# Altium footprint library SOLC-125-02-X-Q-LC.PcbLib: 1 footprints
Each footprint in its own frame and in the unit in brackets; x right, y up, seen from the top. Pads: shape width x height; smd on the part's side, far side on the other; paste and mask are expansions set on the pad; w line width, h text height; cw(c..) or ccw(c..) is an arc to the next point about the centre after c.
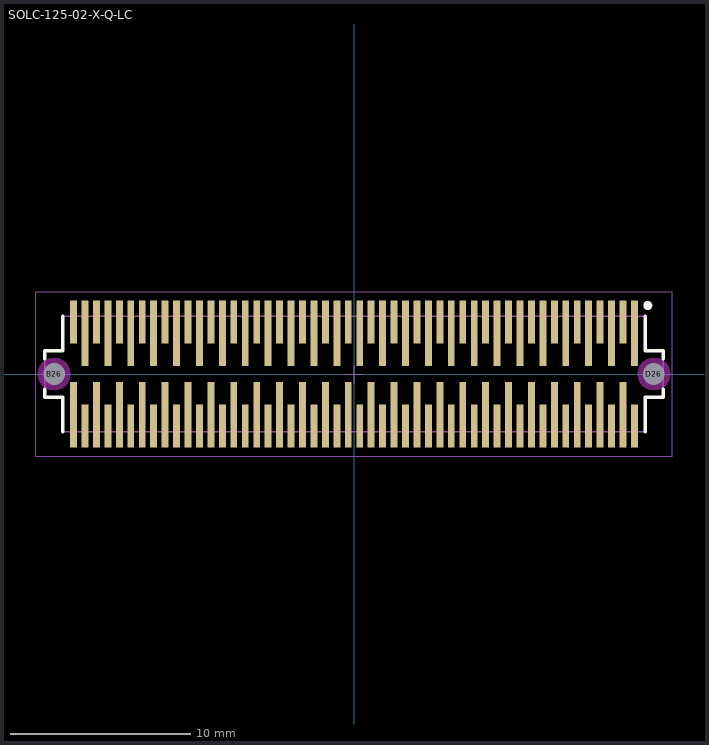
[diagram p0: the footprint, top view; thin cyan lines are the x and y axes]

## SOLC-125-02-X-Q-LC [mm] "1.27mm pitch, 100 pin, socket strip; 4 rows, w/locking clips, SMT"
height 4.62
pads (102):
  rect 0.38x2.36 smd mask+0: A1(14.922,2.885) A2(13.652,2.885) A3(12.383,2.885) A4(11.112,2.885) A5(9.842,2.885) A6(8.572,2.885) A7(7.302,2.885) A8(6.032,2.885) A9(4.763,2.885) A10(3.492,2.885) A11(2.222,2.885) A12(0.953,2.885) A13(-0.318,2.885) A14(-1.587,2.885) A15(-2.857,2.885) A16(-4.127,2.885) A17(-5.397,2.885) A18(-6.667,2.885) A19(-7.938,2.885) A20(-9.207,2.885) A21(-10.477,2.885) A22(-11.747,2.885) A23(-13.018,2.885) A24(-14.287,2.885) A25(-15.557,2.885) D1(15.557,-2.885) D2(14.287,-2.885) D3(13.018,-2.885) D4(11.747,-2.885) D5(10.477,-2.885) D6(9.207,-2.885) D7(7.938,-2.885) D8(6.667,-2.885) D9(5.397,-2.885) D10(4.127,-2.885) D11(2.857,-2.885) D12(1.587,-2.885) D13(0.318,-2.885) D14(-0.953,-2.885) D15(-2.222,-2.885) D16(-3.492,-2.885) D17(-4.763,-2.885) D18(-6.032,-2.885) D19(-7.302,-2.885) D20(-8.572,-2.885) D21(-9.842,-2.885) D22(-11.112,-2.885) D23(-12.383,-2.885) D24(-13.652,-2.885) D25(-14.922,-2.885)
  rect 0.38x3.63 smd mask+0: B1(15.557,2.25) B2(14.287,2.25) B3(13.018,2.25) B4(11.747,2.25) B5(10.477,2.25) B6(9.207,2.25) B7(7.938,2.25) B8(6.667,2.25) B9(5.397,2.25) B10(4.127,2.25) B11(2.857,2.25) B12(1.587,2.25) B13(0.318,2.25) B14(-0.953,2.25) B15(-2.222,2.25) B16(-3.492,2.25) B17(-4.763,2.25) B18(-6.032,2.25) B19(-7.302,2.25) B20(-8.572,2.25) B21(-9.842,2.25) B22(-11.112,2.25) B23(-12.383,2.25) B24(-13.652,2.25) B25(-14.922,2.25) C1(14.922,-2.25) C2(13.652,-2.25) C3(12.383,-2.25) C4(11.112,-2.25) C5(9.842,-2.25) C6(8.572,-2.25) C7(7.302,-2.25) C8(6.032,-2.25) C9(4.763,-2.25) C10(3.492,-2.25) C11(2.222,-2.25) C12(0.953,-2.25) C13(-0.318,-2.25) C14(-1.587,-2.25) C15(-2.857,-2.25) C16(-4.127,-2.25) C17(-5.397,-2.25) C18(-6.667,-2.25) C19(-7.938,-2.25) C20(-9.207,-2.25) C21(-10.477,-2.25) C22(-11.747,-2.25) C23(-13.018,-2.25) C24(-14.287,-2.25) C25(-15.557,-2.25)
  round 1 hole 1.2 unplated mask+0: B26(-16.637,0) D26(16.637,0)
Top Overlay:
  circle w0.25: c16.3,3.8 r0.125
  lines w0.2: -17.15,-0.85 -17.15,-1.3 -16.15,-1.3 -16.15,-3.2 ; -17.15,0.85 -17.15,1.3 -16.15,1.3 -16.15,3.2 ; 16.15,-3.2 16.15,-1.3 17.15,-1.3 17.15,-0.85 ; 16.15,3.2 16.15,1.3 17.15,1.3 17.15,0.85
Keep-Out Layer:
  pour cut-out: -15.729,0 -15.76,0.235 -15.851,0.454 -15.995,0.642 -16.183,0.786 -16.402,0.877 -16.637,0.908 -16.872,0.877 -17.091,0.786 -17.279,0.642 -17.423,0.454 -17.514,0.235 -17.545,0 -17.514,-0.235 -17.423,-0.454 -17.279,-0.642 -17.091,-0.786 -16.872,-0.877 -16.637,-0.908 -16.402,-0.877 -16.183,-0.786 -15.995,-0.642 -15.851,-0.454 -15.76,-0.235
  pour cut-out: 17.545,0 17.514,0.235 17.423,0.454 17.279,0.642 17.091,0.786 16.872,0.877 16.637,0.908 16.402,0.877 16.183,0.786 15.995,0.642 15.851,0.454 15.76,0.235 15.729,0 15.76,-0.235 15.851,-0.454 15.995,-0.642 16.183,-0.786 16.402,-0.877 16.637,-0.908 16.872,-0.877 17.091,-0.786 17.279,-0.642 17.423,-0.454 17.514,-0.235
Mechanical 12:
  lines w0.001: -17.15,-1.3 -16.15,-1.3 -16.15,-3.2 16.15,-3.2 16.15,-1.3 17.15,-1.3 17.15,1.3 16.15,1.3 16.15,3.2 -16.15,3.2 -16.15,1.3 -17.15,1.3 -17.15,-1.3
Mechanical 13:
  lines w0.1: -17.15,-1.3 -16.15,-1.3 -16.15,-3.2 16.15,-3.2 16.15,-1.3 17.15,-1.3 17.15,1.3 16.15,1.3 16.15,3.2 -16.15,3.2 -16.15,1.3 -17.15,1.3 -17.15,-1.3
  text ".Designator" at 0,-0.127 h1.52
Mechanical 15:
  lines w0.05: -0.5,0 0.5,0 ; 0,-0.5 0,0.5 ; -17.65,-4.55 17.65,-4.55 17.65,4.55 -17.65,4.55 -17.65,-4.55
